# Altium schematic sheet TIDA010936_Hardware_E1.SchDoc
size 431 x 279 mm; Date: Not shown in title block; ApprovedBy: Not shown in title block; CheckedBy: Not shown in title block; Author: Not shown in title block; CompanyName: Not shown in title block; DrawnBy: e; Engineer: Not shown in title block; Organization: Not shown in title block; Address1: Not shown in title block; Address2: Not shown in title block; Address3: Not shown in title block; Address4: Not shown in title block; DocumentNumber: 3; Revision: Use project parameter SCH_Rev; SheetNumber: 5; SheetTotal: 5; PageSetup: Record=PageOptions¦CenterHorizontal=True¦CenterVertical=True¦PrintScale=1.00¦XCorrection=1.00¦YCorrection=1.00¦PrintKind=0¦BorderSize=5000000¦LeftOffset=0¦BottomOffset=0¦Orientation=2¦PaperLength=1000¦PaperWidth=1000¦Scale=100¦PaperSource=15¦PrintQuality=600¦MediaType=1¦DitherType=10¦PaperKind=Letter¦PrintScaleMode=1
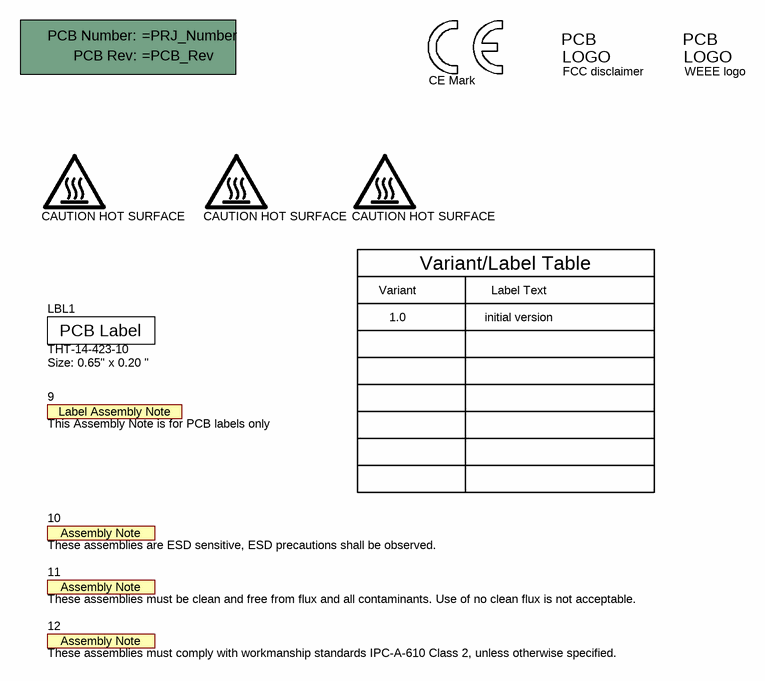
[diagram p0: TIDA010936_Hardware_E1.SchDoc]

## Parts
2  CE Mark  [CE_Mark_5mm]  (no BOM)
4  FCC disclaimer  [FCC_disclaimer]  (no BOM)
5  WEEE logo  [WEEE_Minimum]  (no BOM)
6  CAUTION HOT SURFACE  [IEC_HotSurface_Small]  (no BOM)
7  CAUTION HOT SURFACE  [IEC_HotSurface_Small]  (no BOM)
8  CAUTION HOT SURFACE  [IEC_HotSurface_Small]  (no BOM)
9  This Assembly Note is for PCB labels only  [AssemblyNoteLabel]  (no BOM)
10  These assemblies are ESD sensitive, ESD precautions shall be observed.  [AssemblyNote]  (no BOM)
11  These assemblies must be clean and free from flux and all contaminants. Use of no clean flux is not acceptable.  [AssemblyNote]  (no BOM)
12  These assemblies must comply with workmanship standards IPC-A-610 Class 2, unless otherwise specified.  [AssemblyNote]  (no BOM)
!PCB1  Printed Circuit Board  (value not drawn)  (mechanical)
LBL1  THT-14-423-10  Note: Size: 0.65" x 0.20 "  [Label_650x200]

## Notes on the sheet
- Variant
- Variant/Label Table
- Label Text
- 1.0
- initial version

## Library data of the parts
2 = CMP-0074844-1: SymbolCreator: a0412235
4 = CMP-0074847-1: FCC_disclaimer; Library Reference: Logo
5 = CMP-0074769-3: Manufacturer: Texas Instruments; CompType: IC; AEC Category: Q200
6-8 = CMP-0074837-1: IEC 61010-1 Hot Surface Warning; SymbolCreator: a0412235
9 = CMP-0003616-3
10 = CMP-0077236-1
11 = CMP-0077237-1
12 = CMP-0077238-1
!PCB1 = CMP-0003618-2: Manufacturer: Any
LBL1 = CMP-0003625-1: Thermal Transfer Printable Labels, 0.650" W x 0.200" H - 10,000 per roll; Manufacturer: Brady; CompType: Label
